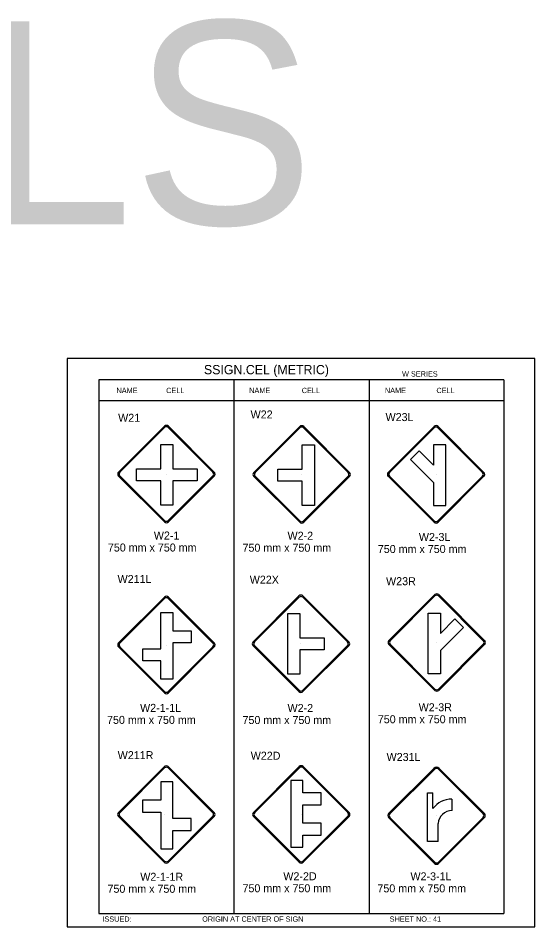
# Model space of a CAD drawing. Extents: x -12 to 6962, y -3756 to 679.
# Drawn here: x 2148.8 to 2342.4, y 225.3 to 565.9 of the extents above; entities that cross this region are included whole.
import ezdxf

# ---------------------------------------------------------------- set-up
doc = ezdxf.new("R2010")
doc.units = 0
for name, color, linetype in [('Level 1', 7, 'Continuous'), ('Level 2', 7, 'Continuous'), ('Level 3', 7, 'Continuous'), ('Level 62', 7, 'Continuous')]:
    doc.layers.add(name, color=color, linetype=linetype)

msp = doc.modelspace()

# ---------------------------------------------------------------- linework, layer by layer
at = {"layer": 'Level 1'}
for p, q in [((2330.8, 430.35), (2179.04, 430.35)), ((2179.04, 430.35), (2179.04, 230.35)), ((2229.63, 430.35), (2229.63, 230.35)), ((2280.36, 430.35), (2280.36, 230.35)), ((2330.8, 430.35), (2330.8, 230.35)), ((2229.63, 422.43), (2179.04, 422.43)), ((2280.21, 422.43), (2229.63, 422.43)), ((2330.8, 422.43), (2280.21, 422.43)), ((2186.43, 395.8), (2203.62, 412.99)), ((2186.93, 395.74), (2203.69, 412.49)), ((2205.06, 412.49), (2221.81, 395.74)), ((2205.12, 412.99), (2222.31, 395.8)), ((2237.12, 395.65), (2254.31, 412.84)), ((2237.62, 395.59), (2254.38, 412.34)), ((2255.75, 412.34), (2272.5, 395.59)), ((2255.81, 412.84), (2273, 395.65)), ((2287.49, 395.68), (2304.68, 412.87)), ((2287.98, 395.62), (2304.74, 412.38)), ((2306.11, 412.38), (2322.87, 395.62)), ((2306.17, 412.87), (2323.37, 395.68)), ((2202.29, 396.99), (2202.29, 406.1)), ((2202.29, 406.1), (2206.83, 406.1)), ((2206.83, 406.1), (2206.83, 396.99)), ((2255.26, 396.87), (2255.26, 405.95)), ((2255.26, 405.95), (2259.8, 405.95)), ((2259.8, 405.95), (2259.8, 383.22)), ((2309.03, 405.98), (2304.46, 405.98)), ((2304.46, 405.98), (2304.46, 398.32)), ((2309.03, 383.25), (2309.03, 405.98)), ((2299.03, 403.78), (2295.81, 400.55)), ((2304.46, 398.32), (2299.03, 403.78)), ((2295.81, 400.55), (2304.46, 391.9)), ((2193.18, 392.45), (2193.18, 396.99)), ((2193.18, 396.99), (2202.29, 396.99)), ((2206.83, 396.99), (2215.91, 396.99)), ((2215.91, 396.99), (2215.91, 392.45)), ((2246.18, 392.33), (2246.18, 396.87)), ((2246.18, 396.87), (2255.26, 396.87)), ((2203.62, 377.11), (2186.43, 394.3)), ((2203.69, 377.61), (2186.93, 394.37)), ((2202.29, 392.45), (2193.18, 392.45)), ((2202.29, 383.37), (2202.29, 392.45)), ((2204.33, 394.98), (2204.33, 394.98)), ((2221.81, 394.37), (2205.06, 377.61)), ((2222.31, 394.3), (2205.12, 377.11)), ((2215.91, 392.45), (2206.83, 392.45)), ((2206.83, 392.45), (2206.83, 383.37)), ((2254.31, 376.96), (2237.12, 394.15)), ((2254.38, 377.46), (2237.62, 394.22)), ((2255.26, 392.33), (2246.18, 392.33)), ((2254.87, 395.05), (2254.87, 395.05)), ((2255.26, 383.22), (2255.26, 392.33)), ((2272.5, 394.22), (2255.75, 377.46)), ((2273, 394.15), (2255.81, 376.96)), ((2304.68, 376.99), (2287.49, 394.19)), ((2304.74, 377.49), (2287.98, 394.25)), ((2304.46, 391.9), (2304.46, 383.25)), ((2305.55, 394.98), (2305.55, 394.98)), ((2322.87, 394.25), (2306.11, 377.49)), ((2323.37, 394.19), (2306.17, 376.99)), ((2206.83, 383.37), (2202.29, 383.37)), ((2259.8, 383.22), (2255.26, 383.22)), ((2304.46, 383.25), (2309.03, 383.25)), ((2186.43, 331.72), (2203.63, 348.91)), ((2186.93, 331.65), (2203.69, 348.41)), ((2205.06, 348.41), (2221.82, 331.65)), ((2205.12, 348.91), (2222.31, 331.71)), ((2236.86, 332.16), (2254.05, 349.35)), ((2237.36, 332.1), (2254.12, 348.86)), ((2255.49, 348.86), (2272.24, 332.1)), ((2255.55, 349.35), (2272.74, 332.16)), ((2287.75, 332.64), (2304.95, 349.84)), ((2288.25, 332.58), (2305.01, 349.34)), ((2306.38, 349.34), (2323.13, 332.58)), ((2306.44, 349.84), (2323.63, 332.64)), ((2202.29, 343.16), (2206.83, 343.16)), ((2202.29, 329.51), (2202.29, 343.16)), ((2206.83, 343.16), (2206.83, 336.33)), ((2249.88, 320.03), (2249.88, 342.76)), ((2249.88, 342.76), (2254.42, 342.76)), ((2254.42, 342.76), (2254.42, 333.65)), ((2302.5, 320.21), (2302.5, 342.94)), ((2302.5, 342.94), (2307.04, 342.94)), ((2307.04, 342.94), (2307.04, 335.31)), ((2307.04, 335.31), (2312.47, 340.74)), ((2312.47, 340.74), (2315.69, 337.54)), ((2315.69, 337.54), (2307.04, 328.89)), ((2206.83, 336.33), (2213.66, 336.33)), ((2213.66, 336.33), (2213.66, 331.79)), ((2204.33, 330.89), (2204.33, 330.89)), ((2213.66, 331.79), (2206.83, 331.79)), ((2206.83, 331.79), (2206.83, 318.14)), ((2254.05, 313.47), (2236.86, 330.67)), ((2254.12, 313.97), (2237.36, 330.73)), ((2254.42, 333.65), (2263.5, 333.65)), ((2254.76, 331.34), (2254.76, 331.34)), ((2272.24, 330.73), (2255.49, 313.97)), ((2272.74, 330.67), (2255.55, 313.47)), ((2263.5, 333.65), (2263.5, 329.11)), ((2304.95, 313.96), (2287.75, 331.15)), ((2305.01, 314.45), (2288.25, 331.21)), ((2305.65, 331.82), (2305.65, 331.82)), ((2323.13, 331.21), (2306.38, 314.45)), ((2323.63, 331.15), (2306.44, 313.96)), ((2203.63, 313.03), (2186.43, 330.22)), ((2203.69, 313.53), (2186.93, 330.28)), ((2195.47, 324.97), (2195.47, 329.51)), ((2195.47, 329.51), (2202.29, 329.51)), ((2221.82, 330.28), (2205.06, 313.53)), ((2222.31, 330.22), (2205.12, 313.03)), ((2254.42, 329.11), (2254.42, 320.03)), ((2263.5, 329.11), (2254.42, 329.11)), ((2307.04, 328.89), (2307.04, 320.21)), ((2202.29, 324.97), (2195.47, 324.97)), ((2202.29, 318.14), (2202.29, 324.97)), ((2307.04, 320.21), (2302.5, 320.21)), ((2206.83, 318.14), (2202.29, 318.14)), ((2254.42, 320.03), (2249.88, 320.03)), ((2186.39, 268.16), (2203.59, 285.35)), ((2186.89, 268.1), (2203.65, 284.86)), ((2205.02, 284.86), (2221.78, 268.1)), ((2205.08, 285.35), (2222.27, 268.16)), ((2236.95, 268.2), (2254.15, 285.39)), ((2237.45, 268.14), (2254.21, 284.9)), ((2255.58, 284.9), (2272.34, 268.14)), ((2255.64, 285.39), (2272.83, 268.2)), ((2287.65, 267.74), (2304.6, 284.69)), ((2288.15, 267.67), (2304.91, 284.43)), ((2306.28, 284.43), (2323.04, 267.67)), ((2306.58, 284.69), (2323.53, 267.74)), ((2206.79, 279.6), (2202.25, 279.6)), ((2202.25, 279.6), (2202.25, 272.78)), ((2206.79, 265.95), (2206.79, 279.6)), ((2255.48, 280.13), (2250.94, 280.13)), ((2250.94, 280.13), (2250.94, 255.12)), ((2255.48, 275.58), (2255.48, 280.13)), ((2202.25, 272.78), (2195.43, 272.78)), ((2195.43, 272.78), (2195.43, 268.24)), ((2262.31, 275.58), (2255.48, 275.58)), ((2262.31, 271.04), (2262.31, 275.58)), ((2302.26, 257.28), (2302.26, 275.55)), ((2302.26, 275.55), (2304.24, 275.55)), ((2304.24, 269.67), (2304.24, 275.55)), ((2311.28, 273.17), (2311.34, 268.86)), ((2255.48, 271.04), (2262.31, 271.04)), ((2255.48, 264.21), (2255.48, 271.04)), ((2203.59, 249.47), (2186.39, 266.67)), ((2203.65, 249.97), (2186.89, 266.73)), ((2195.43, 268.24), (2202.25, 268.24)), ((2202.25, 268.24), (2202.25, 254.59)), ((2203.79, 267.4), (2203.79, 267.4)), ((2221.78, 266.73), (2205.02, 249.97)), ((2222.27, 266.67), (2205.08, 249.47)), ((2213.62, 265.95), (2206.79, 265.95)), ((2213.62, 261.41), (2213.62, 265.95)), ((2254.15, 249.51), (2236.95, 266.71)), ((2254.21, 250.01), (2237.45, 266.77)), ((2254.85, 267.38), (2254.85, 267.38)), ((2272.34, 266.77), (2255.58, 250.01)), ((2272.83, 266.71), (2255.64, 249.51)), ((2304.85, 249.05), (2287.65, 266.24)), ((2304.91, 249.55), (2288.15, 266.3)), ((2305.55, 266.92), (2305.55, 266.92)), ((2323.04, 266.3), (2306.28, 249.55)), ((2323.53, 266.24), (2306.34, 249.05)), ((2262.31, 264.21), (2255.48, 264.21)), ((2262.31, 259.67), (2262.31, 264.21)), ((2306.22, 257.28), (2306.22, 264.01)), ((2206.79, 254.59), (2206.79, 261.41)), ((2206.79, 261.41), (2213.62, 261.41)), ((2255.48, 255.12), (2255.48, 259.67)), ((2255.48, 259.67), (2262.31, 259.67)), ((2306.22, 257.28), (2302.26, 257.28)), ((2202.25, 254.59), (2206.79, 254.59)), ((2250.94, 255.12), (2255.48, 255.12)), ((2179.04, 230.35), (2330.8, 230.35))]:
    msp.add_line(p, q, dxfattribs=at)
for centre, radius, start, end in [((2204.37, 412.24), 1.06, 45, 135), ((2204.37, 411.81), 0.969, 45, 135), ((2255.06, 412.09), 1.06, 45, 135), ((2255.06, 411.66), 0.969, 45, 135), ((2305.43, 412.13), 1.06, 45, 135), ((2305.43, 411.69), 0.969, 45, 135), ((2187.18, 395.05), 1.06, 135, 225), ((2187.61, 395.05), 0.969, 135, 225), ((2221.13, 395.05), 0.969, 315, 45), ((2221.56, 395.05), 1.06, 315, 45), ((2237.87, 394.9), 1.06, 135, 225), ((2238.3, 394.9), 0.969, 135, 225), ((2271.82, 394.9), 0.969, 315, 45), ((2272.25, 394.9), 1.06, 315, 45), ((2288.23, 394.93), 1.06, 135, 225), ((2288.67, 394.93), 0.969, 135, 225), ((2322.18, 394.93), 0.969, 315, 45), ((2322.62, 394.93), 1.06, 315, 45), ((2204.37, 377.86), 1.06, 225, 315), ((2204.37, 378.29), 0.969, 225, 315), ((2255.06, 377.71), 1.06, 225, 315), ((2255.06, 378.15), 0.969, 225, 315), ((2305.43, 377.74), 1.06, 225, 315), ((2305.43, 378.18), 0.969, 225, 315), ((2204.37, 348.16), 1.06, 45, 135), ((2204.37, 347.72), 0.969, 45, 135), ((2254.8, 348.61), 1.06, 45, 135), ((2254.8, 348.17), 0.969, 45, 135), ((2305.69, 349.09), 1.06, 45, 135), ((2305.69, 348.65), 0.969, 45, 135), ((2187.18, 330.97), 1.06, 135, 225), ((2187.62, 330.97), 0.969, 135, 225), ((2221.13, 330.97), 0.969, 315, 45), ((2221.57, 330.97), 1.06, 315, 45), ((2237.61, 331.41), 1.06, 135, 225), ((2238.04, 331.41), 0.969, 135, 225), ((2271.56, 331.41), 0.969, 315, 45), ((2271.99, 331.41), 1.06, 315, 45), ((2288.5, 331.9), 1.06, 135, 225), ((2288.94, 331.9), 0.969, 135, 225), ((2322.45, 331.9), 0.969, 315, 45), ((2322.89, 331.9), 1.06, 315, 45), ((2204.37, 314.21), 0.969, 225, 315), ((2254.8, 314.22), 1.06, 225, 315), ((2254.8, 314.66), 0.969, 225, 315), ((2305.69, 314.7), 1.06, 225, 315), ((2305.69, 315.14), 0.969, 225, 315), ((2204.37, 313.77), 1.06, 225, 315), ((2204.33, 284.61), 1.06, 45, 135), ((2204.33, 284.17), 0.969, 45, 135), ((2254.89, 284.65), 1.06, 45, 135), ((2254.89, 284.21), 0.969, 45, 135), ((2305.59, 283.75), 0.969, 45, 135), ((2311.41, 264.08), 9.1, 90.7317, 142.0366), ((2187.14, 267.41), 1.06, 135, 225), ((2187.58, 267.41), 0.969, 135, 225), ((2221.09, 267.41), 0.969, 315, 45), ((2221.53, 267.41), 1.06, 315, 45), ((2237.7, 267.45), 1.06, 135, 225), ((2238.14, 267.45), 0.969, 135, 225), ((2271.65, 267.45), 0.969, 315, 45), ((2272.09, 267.45), 1.06, 315, 45), ((2288.4, 266.99), 1.06, 135, 225), ((2288.84, 266.99), 0.969, 135, 225), ((2311.35, 263.73), 5.13, 89.4988, 176.8756), ((2322.35, 266.99), 0.969, 315, 45), ((2322.79, 266.99), 1.06, 315, 45), ((2204.33, 250.22), 1.06, 225, 315), ((2204.33, 250.66), 0.969, 225, 315), ((2254.89, 250.26), 1.06, 225, 315), ((2254.89, 250.7), 0.969, 225, 315), ((2305.59, 249.8), 1.06, 225, 315), ((2305.59, 250.23), 0.969, 225, 315)]:
    msp.add_arc(centre, radius, start, end, dxfattribs=at)
at = {"layer": 'Level 3'}
msp.add_arc((2305.59, 283.7), 1.4, 45, 135, dxfattribs=at)
at = {"layer": 'Level 62'}
msp.add_lwpolyline([(2167.17, 225.31), (2342.43, 225.31), (2342.43, 438.4), (2167.17, 438.4)], close=True, dxfattribs=at)

# ---------------------------------------------------------------- texts
at = {"layer": 'Level 2'}
for s, p in [('W21', (2186.28, 414.63)), ('W22', (2235.91, 415.88)), ('W23L', (2286.49, 414.9)), ('W211L', (2186.06, 354.19)), ('W22X', (2235.6, 353.94)), ('W23R', (2286.68, 353.38)), ('W211R', (2186.11, 288.16)), ('W22D', (2235.96, 287.95)), ('W231L', (2286.88, 287.48))]:
    msp.add_text(s, height=3, dxfattribs=at).set_placement(p)
at = {"layer": 'Level 3'}
for s, height, p in [('W-SERIES CELLS', 76.1938, (1404.77, 488.61)), ('SSIGN.CEL (METRIC)', 3.4642, (2218.43, 432.46)), ('W SERIES', 1.979, (2292.67, 431.59)), ('NAME', 1.98, (2185.66, 425.39)), ('CELL', 1.98, (2204.26, 425.39)), ('NAME', 1.98, (2235.38, 425.39)), ('CELL', 1.98, (2255.08, 425.39)), ('NAME', 1.98, (2286.25, 425.39)), ('CELL', 1.98, (2305.55, 425.39)), ('W2-1', 3, (2199.65, 370.5)), ('W2-2', 3, (2249.76, 370.42)), ('W2-3L', 3, (2298.97, 369.94)), ('750 mm x 750 mm', 3, (2182.43, 366)), ('750 mm x 750 mm', 3, (2232.88, 365.92)), ('750 mm x 750 mm', 3, (2283.59, 365.44)), ('W2-1-1L', 3, (2194.5, 305.89)), ('W2-2', 3, (2249.76, 305.83)), ('W2-3R', 3, (2298.89, 306.12)), ('750 mm x 750 mm', 3, (2182.12, 301.39)), ('750 mm x 750 mm', 3, (2232.88, 301.33)), ('750 mm x 750 mm', 3, (2283.59, 301.62)), ('W2-1-1R', 3, (2194.57, 242.57)), ('W2-2D', 3, (2248.18, 242.76)), ('W2-3-1L', 3, (2295.82, 242.73)), ('750 mm x 750 mm', 3, (2182.28, 238.07)), ('750 mm x 750 mm', 3, (2232.88, 238.26)), ('750 mm x 750 mm', 3, (2283.44, 238.23)), ('ISSUED:', 1.98, (2180.38, 227.23)), ('ORIGIN AT CENTER OF SIGN', 1.9795, (2217.77, 227.23)), ('SHEET NO.: 41', 1.9795, (2288.03, 227.23))]:
    msp.add_text(s, height=height, dxfattribs=at).set_placement(p)

doc.saveas('drawing.dxf')
